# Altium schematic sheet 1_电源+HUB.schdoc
size 431 x 309 mm; Symbol: Sheet-Symbol_A3; Device: Sheet-Symbol_A3; Company: 嘉立创EDA; Version: V1.0; Page Size: A3; @Project Name: 基于stm32和ttp233的触摸键盘; @Page Count: 3; @Update Date: 2024-11-03; @Create Date: 2024-11-03; @Schematic Name: Schematic1_1; @Page No: 1; @Page Name: 电源+HUB; Title Block Position: 3; Width: 1170; Height: 825; Region Start: 1; X Region Count: 6; Y Region Count: 4; Blade Width: 10; @Board Name: Board1; @Create Time: 21:01:00; @Update Time: 21:01:07
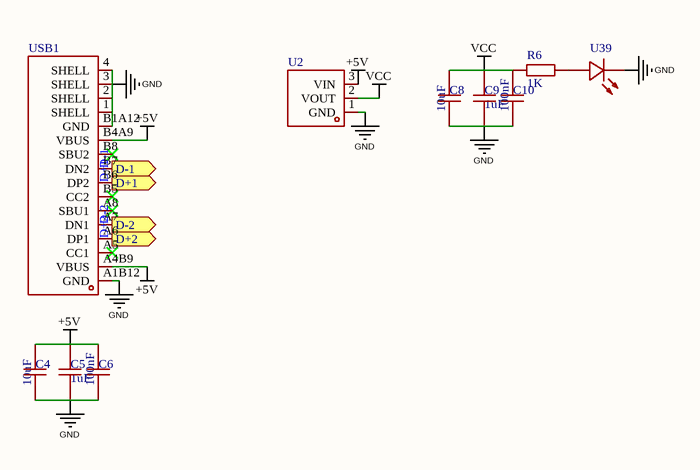
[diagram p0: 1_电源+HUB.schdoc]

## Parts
C4  10uF  [C0603]
C5  1uF  [C0603]
C6  100nF  [C0603]
C8  10uF  [C0603]
C9  1uF  [C0603]
C10  100nF  [C0603]
R6  1K  [R0603]  (value not drawn)
U2  AMS1117-3.3V-JSM  [SOT-89-3_L4.5-W2.5-P1.50-LS4.2-TL]  (value not drawn)
U39  LED白  [LED0603-RD_WHITE]  (value not drawn)
USB1  TYPE-C16PIN  [USB-C-SMD_TYPE-C16PIN]  (value not drawn)

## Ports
D+1 (out), D+2 (out), D-1 (out), D-2 (out)

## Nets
+5V: C4.2 C5.2 C6.2 U2.3(VIN) USB1.A4B9(VBUS) USB1.B4A9(VBUS)
GND: C4.1 C5.1 C6.1 C8.1 C9.1 C10.1 U2.1(GND) U39.1(K) USB1.1(SHELL) USB1.2(SHELL) USB1.3(SHELL) USB1.4(SHELL) USB1.A1B12(GND) USB1.B1A12(GND)
VCC: C8.2 C9.2 C10.2 R6.1 U2.2(VOUT)
D+1: USB1.B6(DP2) ; port D+1
D+2: USB1.A6(DP1) ; port D+2
D-1: USB1.B7(DN2) ; port D-1
D-2: USB1.A7(DN1) ; port D-2
NetR6_2: R6.2 U39.2(A)

Not connected (* = marked no-connect by the designer): USB1 A5(CC1)* A8(SBU1)* B5(CC2)* B8(SBU2)*

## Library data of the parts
C4 C8 = CL10A106KP8NNNC: 容值:10uF;精度:±10%;额定电压:10V;材质(温度系数):X5R;; Manufacturer: SAMSUNG(三星); Add into BOM: yes; Tolerance: ±10%; Voltage Rated: 10V; Temperature Coefficient: X5R
C5 C9 = CL10A105KB8NNNC: 容值:1uF;精度:±10%;额定电压:50V;材质(温度系数):X5R;; Manufacturer: SAMSUNG(三星); Add into BOM: yes; Tolerance: ±10%; Voltage Rated: 50V; Temperature Coefficient: X5R
C6 C10 = CC0603KRX7R9BB104: 容值:100nF;精度:±10%;额定电压:50V;材质(温度系数):X7R;; Manufacturer: YAGEO(国巨); Add into BOM: yes; Tolerance: ±10%; Voltage Rated: 50V; Temperature Coefficient: X7R
R6 = Res_0603: Symbol: 电阻; Convert to PCB: yes
U2 = AMS1117-3.3V-JSM: 输出类型:固定;最大输入电压:15V;输出电压:3.3V;输出电流:1.2A;; Manufacturer: JSMSEMI(杰盛微); Add into BOM: yes; Output Type: 固定; Maximum Input Voltage: 15V; Output Voltage: 3.3V; Output Current: 1.2A
U39 = LED白: Add into BOM: yes
USB1 = TYPE-C16PIN: 连接器类型:Type-C;标准:USB 3.1;公母:母;安装方式:卧贴;触点数量:16P;端口数量:1;额定电流 - 电源:3A;工作温度范围:-40℃~+85℃;; Manufacturer: SHOU HAN(首韩); Add into BOM: yes; Connector Type: Type-C; Gender: 母; Number of Contacts: 16P; Number of Ports: 1; Current Rating - Power (Max): 3A; Rated Voltage (Max): 30V; Connect-Disconnect Life: 1万次; Core Colour: 黑色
